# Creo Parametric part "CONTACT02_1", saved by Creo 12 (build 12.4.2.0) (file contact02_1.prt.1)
Units: Custom; MM, KILOGRAM, SECS

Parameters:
  PTC_WM_ITERATION = "0"
  PTC_WM_VERSION = "-.0"
  PTC_WM_LIFECYCLE_STATE = "In Work"
  PTC_WM_LIFECYCLE = "MO_CADDocument"
  PTC_WM_CREATED_BY = "Maximilian Roepper (Z0017RMS: MO)"
  PTC_WM_CREATED_ON = "18-Sep-26 11:36:42 AM"
  PTC_WM_MODIFIED_BY = "Maximilian Roepper (Z0017RMS: MO)"
  PTC_WM_MODIFIED_ON = "18-Sep-26 11:36:46 AM"
  PDMLINKNUMBER = "PDM000071455083"
  PTC_WM_NAME = "contact02_1.prt"
  PTC_WM_NUMBER = "PDM000071455083"

Other parameters: WEIGHT, WEIGHT_FACTOR, WEIGHT_ADD, _MASS_TEMP, _DIFF_TEMP, MC_ERRORS, SUPPLIER

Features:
  1. coordinate system
  2. datum plane "PRT_YZ"
  3. datum plane "PRT_XY"
  4. datum plane "PRT_XZ"
  5. coordinate system
  6. datum axis
  7. datum axis
  8. datum axis
  9. coordinate system
  10. imported feature

Other named items: PRT, SIEMENS_MO, DRW_VIEW_ORG, PRT_X, PRT_Y, PRT_Z, CS0, ROUGH_GROB

Layers: 00_STD_CSYS-KSYS, 01_STD_PLANES-EBENEN, 02_STD_AXES-ACHSEN, 03_STD_CSYS-KSYS, 24_IMPORT_FEAT-IMPORT_KE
